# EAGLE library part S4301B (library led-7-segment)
Single Digit Seven-Segment Display (cathode common) Source: LITEON .. S4301B.pdf
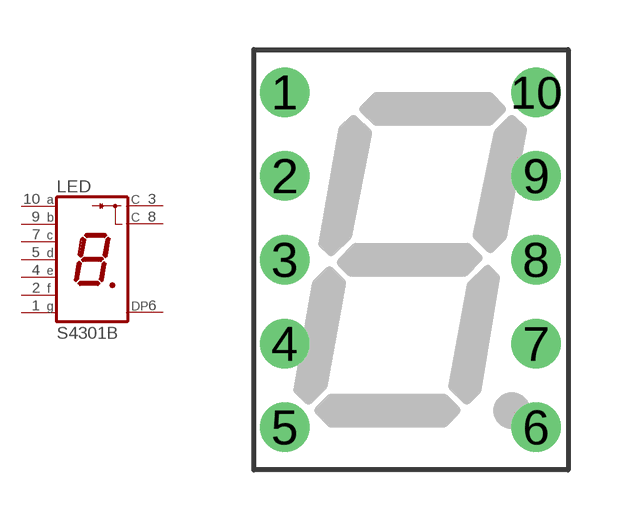
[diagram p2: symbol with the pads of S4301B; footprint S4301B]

Designator prefix LED

## S4301B (OC_FARNELL: unknown; OC_NEWARK: unknown)  [S4301B]
1  G  pas
2  F  pas
3  C  pas
4  E  pas
5  D  pas
6  DP  pas
7  C  pas
8  C  pas
9  B  pas
10  A  pas

## Footprint S4301B (pad centres in mm)
Single Digit LED Numeric Display Source: LITEON .. S4301B.pdf
drill 0.9 pad 1.5 round: 1 -3.81,5.08; 2 -3.81,2.54; 3 -3.81,0; 4 -3.81,-2.54; 5 -3.81,-5.08; 6 3.81,-5.08; 7 3.81,-2.54; 8 3.81,0; 9 3.81,2.54; 10 3.81,5.08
